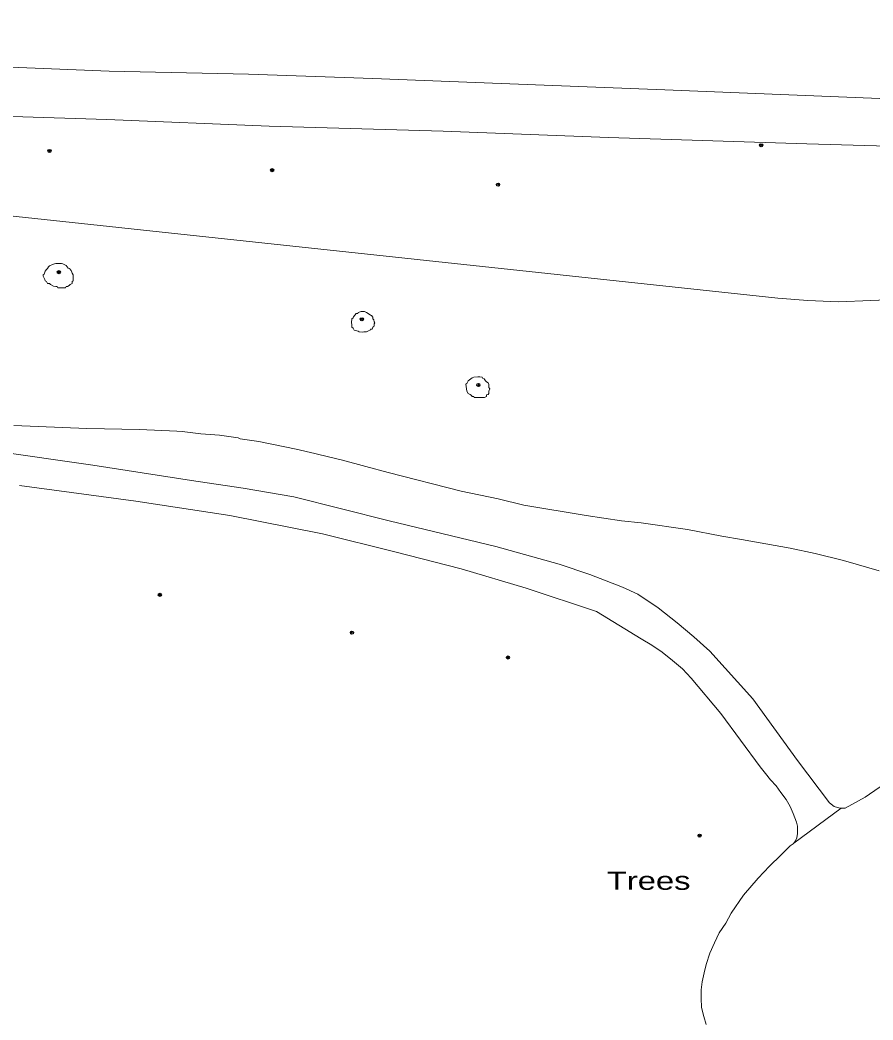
# Model space of a CAD drawing. Extents: x 528790 to 529292, y 179350 to 179856.
# Drawn here: x 528872.6 to 528954.9, y 179684.2 to 179780.7 of the extents above; entities that cross this region are included whole.
import ezdxf

# ---------------------------------------------------------------- set-up
doc = ezdxf.new("R2010")
doc.units = 0
doc.header["$LTSCALE"] = 0.6
doc.header["$PDMODE"] = 32
doc.header["$PDSIZE"] = 0.3
doc.layers.add('1', color=7, linetype='Continuous', lineweight=13)
doc.layers.add('2', color=7, linetype='Continuous', lineweight=13)
doc.layers.add('3', color=7, linetype='Continuous')
doc.layers.add('5', color=7, linetype='Continuous')

msp = doc.modelspace()

# ---------------------------------------------------------------- linework, layer by layer
at = {"layer": '1'}
for points in [[(528995.96, 179785.29), (528808.03, 179792.34), (528790.22, 179792.969), (528790.22, 179779.158), (528797.95, 179778.9), (528811.7, 179778.4), (528825.8, 179777.8), (528841.4, 179777.2), (528857, 179776.75), (528870, 179776.25), (528881.15, 179775.8), (528894.6, 179775.5), (528906.6, 179775.1), (528919, 179774.6), (528934.8, 179774), (528959.55, 179773)], [(528959.55, 179773), (528934.8, 179774), (528919, 179774.6), (528906.6, 179775.1), (528894.6, 179775.5), (528881.15, 179775.8), (528870, 179776.25), (528857, 179776.75), (528841.4, 179777.2), (528825.8, 179777.8), (528811.7, 179778.4), (528797.95, 179778.9), (528790.22, 179779.158), (528790.22, 179774.277), (528823.7, 179773.15), (528843.9, 179772.4), (528859.6, 179771.8), (528880.95, 179771.15), (528896.6, 179770.5), (528913.4, 179770), (528929.35, 179769.4), (528948.5, 179768.8), (528965.3, 179768.3)], [(528965.3, 179768.3), (528948.5, 179768.8), (528929.35, 179769.4), (528913.4, 179770), (528896.6, 179770.5), (528880.95, 179771.15), (528859.6, 179771.8), (528843.9, 179772.4), (528823.7, 179773.15), (528790.22, 179774.277), (528790.22, 179770.55), (528945.7, 179753.9), (528948.6, 179753.65), (528951.55, 179753.55), (528957.8, 179753.8)], [(528957.8, 179753.8), (528951.55, 179753.55), (528948.6, 179753.65), (528945.7, 179753.9), (528790.22, 179770.55)], [(528955.5, 179727.55), (528952.05, 179728.55), (528949.3, 179729.25), (528946.9, 179729.75), (528942.2, 179730.6), (528940.3, 179730.9), (528937, 179731.55), (528932.5, 179732.2), (528930.6, 179732.4), (528927.2, 179732.9), (528921.2, 179733.9), (528918.7, 179734.5), (528915.15, 179735.25), (528908.1, 179737.05), (528905.95, 179737.65), (528903.7, 179738.25), (528901.4, 179738.8), (528901, 179738.9), (528899.2, 179739.3), (528895.6, 179740.05), (528893.8, 179740.3), (528893.6, 179740.4), (528891.8, 179740.65), (528890, 179740.8), (528888.2, 179741), (528887.7, 179741.05), (528884.1, 179741.2), (528879, 179741.3), (528871.95, 179741.6)], [(528871.95, 179741.6), (528879, 179741.3), (528884.1, 179741.2), (528887.7, 179741.05), (528888.2, 179741), (528890, 179740.8), (528891.8, 179740.65), (528893.6, 179740.4), (528893.8, 179740.3), (528895.6, 179740.05), (528899.2, 179739.3), (528901, 179738.9), (528901.4, 179738.8), (528903.7, 179738.25), (528905.95, 179737.65), (528908.1, 179737.05), (528915.15, 179735.25), (528918.7, 179734.5), (528921.2, 179733.9), (528927.2, 179732.9), (528930.6, 179732.4), (528932.5, 179732.2), (528937, 179731.55), (528940.3, 179730.9), (528942.2, 179730.6), (528946.9, 179729.75), (528949.3, 179729.25), (528952.05, 179728.55), (528955.5, 179727.55)], [(528869.9, 179739.15), (528879.6, 179737.75), (528889.1, 179736.3), (528894.1, 179735.55), (528899, 179734.7), (528908.2, 179732.4), (528918.5, 179729.9), (528924.6, 179728.2), (528927.55, 179727.2), (528929.15, 179726.6), (528930.7, 179726), (528932.2, 179725.3), (528934.15, 179724), (528936, 179722.55), (528937.6, 179721.2), (528939.15, 179719.8), (528943.3, 179715.2), (528947.6, 179709.25), (528950.7, 179705.15), (528951.15, 179704.8), (528951.7, 179704.65), (528951.82, 179704.65), (528952.2, 179704.65), (528954.15, 179705.7), (528955.5, 179706.65)], [(528872.5, 179735.8), (528883.75, 179734.3), (528892.8, 179732.9), (528901.75, 179731.15), (528908.75, 179729.4), (528915.15, 179727.75), (528921.4, 179725.9), (528928.2, 179723.65), (528932.5, 179721), (528933.55, 179720.4), (528934.55, 179719.7), (528935.55, 179718.9), (528936.5, 179718.1), (528937.35, 179717.2), (528940.2, 179713.8), (528944, 179708.65), (528944.5, 179708), (528945, 179707.4), (528945.55, 179706.8), (528946, 179706.15), (528946.5, 179705.5), (528946.9, 179704.8), (528947.2, 179704.15), (528947.5, 179703.3), (528947.6, 179702.9), (528947.6, 179702.2), (528947.55, 179701.8), (528947.4, 179701.5), (528947.24, 179701.26), (528951.82, 179704.65), (528951.7, 179704.65), (528951.15, 179704.8), (528950.7, 179705.15), (528947.6, 179709.25), (528943.3, 179715.2), (528939.15, 179719.8), (528937.6, 179721.2), (528936, 179722.55), (528934.15, 179724), (528932.2, 179725.3), (528930.7, 179726), (528929.15, 179726.6), (528927.55, 179727.2), (528924.6, 179728.2), (528918.5, 179729.9), (528908.2, 179732.4), (528899, 179734.7), (528894.1, 179735.55), (528889.1, 179736.3), (528879.6, 179737.75), (528869.9, 179739.15)], [(528938.8, 179683.75), (528938.55, 179684.55), (528938.35, 179685.4), (528938.3, 179686.3), (528938.3, 179687.1), (528938.4, 179687.9), (528938.6, 179688.75), (528938.8, 179689.55), (528939.15, 179690.65), (528939.6, 179691.65), (528940.05, 179692.6), (528940.7, 179693.55), (528941.2, 179694.5), (528942.4, 179696.25), (528943.8, 179697.9), (528944.9, 179699.05), (528946, 179700.1), (528946.9, 179701), (528947.2, 179701.2), (528947.24, 179701.26), (528947.4, 179701.5), (528947.55, 179701.8), (528947.6, 179702.2), (528947.6, 179702.9), (528947.5, 179703.3), (528947.2, 179704.15), (528946.9, 179704.8), (528946.5, 179705.5), (528946, 179706.15), (528945.55, 179706.8), (528945, 179707.4), (528944.5, 179708), (528944, 179708.65), (528940.2, 179713.8), (528937.35, 179717.2), (528936.5, 179718.1), (528935.55, 179718.9), (528934.55, 179719.7), (528933.55, 179720.4), (528932.5, 179721), (528928.2, 179723.65), (528921.4, 179725.9), (528915.15, 179727.75), (528908.75, 179729.4), (528901.75, 179731.15), (528892.8, 179732.9), (528883.75, 179734.3), (528872.5, 179735.8)], [(528955.5, 179706.65), (528954.15, 179705.7), (528952.2, 179704.65), (528951.82, 179704.65), (528947.24, 179701.26), (528947.2, 179701.2), (528946.9, 179701), (528946, 179700.1), (528944.9, 179699.05), (528943.8, 179697.9), (528942.4, 179696.25), (528941.2, 179694.5), (528940.7, 179693.55), (528940.05, 179692.6), (528939.6, 179691.65), (528939.15, 179690.65), (528938.8, 179689.55), (528938.6, 179688.75), (528938.4, 179687.9), (528938.3, 179687.1), (528938.3, 179686.3), (528938.35, 179685.4), (528938.55, 179684.55), (528938.8, 179683.75)]]:
    msp.add_lwpolyline(points, dxfattribs=at)
for points in [[(528875.1, 179755.5), (528875, 179755.55), (528874.95, 179755.7), (528874.8, 179756), (528874.8, 179756.15), (528874.9, 179756.2), (528875, 179756.5), (528875.1, 179756.65), (528875.2, 179756.75), (528875.3, 179756.9), (528875.4, 179757), (528875.7, 179757.15), (528875.9, 179757.2), (528876, 179757.25), (528876.2, 179757.25), (528876.55, 179757.25), (528876.7, 179757.2), (528877, 179757.05), (528877.1, 179756.9), (528877.2, 179756.8), (528877.35, 179756.75), (528877.4, 179756.65), (528877.5, 179756.55), (528877.55, 179756.4), (528877.6, 179756.3), (528877.7, 179756.15), (528877.7, 179755.55), (528877.6, 179755.5), (528877.6, 179755.3), (528877.4, 179755.2), (528877.3, 179755.1), (528877.15, 179755), (528877, 179755), (528876.95, 179754.9), (528876.2, 179754.9), (528876.15, 179755), (528876, 179755), (528875.8, 179755.05), (528875.5, 179755.2), (528875.4, 179755.3), (528875.2, 179755.3)], [(528876.95, 179754.9), (528877, 179755), (528877.15, 179755), (528877.3, 179755.1), (528877.4, 179755.2), (528877.6, 179755.3), (528877.6, 179755.5), (528877.7, 179755.55), (528877.7, 179756.15), (528877.6, 179756.3), (528877.55, 179756.4), (528877.5, 179756.55), (528877.4, 179756.65), (528877.35, 179756.75), (528877.2, 179756.8), (528877.1, 179756.9), (528877, 179757.05), (528876.7, 179757.2), (528876.55, 179757.25), (528876.2, 179757.25), (528876, 179757.25), (528875.9, 179757.2), (528875.7, 179757.15), (528875.4, 179757), (528875.3, 179756.9), (528875.2, 179756.75), (528875.1, 179756.65), (528875, 179756.5), (528874.9, 179756.2), (528874.8, 179756.15), (528874.8, 179756), (528874.95, 179755.7), (528875, 179755.55), (528875.1, 179755.5), (528875.2, 179755.3), (528875.4, 179755.3), (528875.5, 179755.2), (528875.8, 179755.05), (528876, 179755), (528876.15, 179755), (528876.2, 179754.9)], [(528905, 179752.4), (528905.15, 179752.4), (528905.2, 179752.5), (528905.5, 179752.6), (528905.8, 179752.6), (528906, 179752.5), (528906.15, 179752.4), (528906.4, 179752.25), (528906.5, 179752.2), (528906.6, 179752.05), (528906.6, 179751.9), (528906.7, 179751.8), (528906.75, 179751.6), (528906.8, 179751.5), (528906.75, 179751.4), (528906.75, 179751.25), (528906.7, 179751.15), (528906.6, 179751.1), (528906.55, 179750.9), (528906.4, 179750.9), (528906.35, 179750.8), (528906.2, 179750.75), (528906, 179750.65), (528905.75, 179750.65), (528905.6, 179750.6), (528905.3, 179750.65), (528905.2, 179750.7), (528904.8, 179750.8), (528904.7, 179751), (528904.6, 179751.1), (528904.6, 179751.3), (528904.55, 179751.55), (528904.6, 179751.9), (528904.7, 179752), (528904.75, 179752.1)], [(528906, 179750.65), (528906.2, 179750.75), (528906.35, 179750.8), (528906.4, 179750.9), (528906.55, 179750.9), (528906.6, 179751.1), (528906.7, 179751.15), (528906.75, 179751.25), (528906.75, 179751.4), (528906.8, 179751.5), (528906.75, 179751.6), (528906.7, 179751.8), (528906.6, 179751.9), (528906.6, 179752.05), (528906.5, 179752.2), (528906.4, 179752.25), (528906.15, 179752.4), (528906, 179752.5), (528905.8, 179752.6), (528905.5, 179752.6), (528905.2, 179752.5), (528905.15, 179752.4), (528905, 179752.4), (528904.75, 179752.1), (528904.7, 179752), (528904.6, 179751.9), (528904.55, 179751.55), (528904.6, 179751.3), (528904.6, 179751.1), (528904.7, 179751), (528904.8, 179750.8), (528905.2, 179750.7), (528905.3, 179750.65), (528905.6, 179750.6), (528905.75, 179750.65)], [(528917.4, 179744.3), (528917.6, 179744.4), (528917.6, 179744.55), (528917.75, 179744.6), (528917.8, 179744.7), (528917.8, 179744.9), (528917.9, 179745.15), (528917.8, 179745.25), (528917.8, 179745.55), (528917.75, 179745.7), (528917.6, 179745.8), (528917.5, 179745.9), (528917.35, 179746.1), (528917.2, 179746.15), (528917.15, 179746.25), (528916.95, 179746.3), (528916.75, 179746.3), (528916.35, 179746.25), (528916.2, 179746.2), (528915.95, 179746), (528915.8, 179745.9), (528915.7, 179745.65), (528915.6, 179745.6), (528915.7, 179744.9), (528915.8, 179744.7), (528916, 179744.6), (528916.15, 179744.5), (528916.2, 179744.4), (528916.35, 179744.4), (528916.4, 179744.3)], [(528916.15, 179744.5), (528916, 179744.6), (528915.8, 179744.7), (528915.7, 179744.9), (528915.6, 179745.6), (528915.7, 179745.65), (528915.8, 179745.9), (528915.95, 179746), (528916.2, 179746.2), (528916.35, 179746.25), (528916.75, 179746.3), (528916.95, 179746.3), (528917.15, 179746.25), (528917.2, 179746.15), (528917.35, 179746.1), (528917.5, 179745.9), (528917.6, 179745.8), (528917.75, 179745.7), (528917.8, 179745.55), (528917.8, 179745.25), (528917.9, 179745.15), (528917.8, 179744.9), (528917.8, 179744.7), (528917.75, 179744.6), (528917.6, 179744.55), (528917.6, 179744.4), (528917.4, 179744.3), (528916.4, 179744.3), (528916.35, 179744.4), (528916.2, 179744.4)]]:
    msp.add_lwpolyline(points, close=True, dxfattribs=at)
at = {"layer": '2'}
msp.add_line((528947.24, 179701.26), (528951.82, 179704.65), dxfattribs=at)
for points in [[(528790.22, 179779.158), (528797.95, 179778.9), (528811.7, 179778.4), (528825.8, 179777.8), (528841.4, 179777.2), (528857, 179776.75), (528870, 179776.25), (528881.15, 179775.8), (528894.6, 179775.5), (528906.6, 179775.1), (528919, 179774.6), (528934.8, 179774), (528959.55, 179773)], [(528790.22, 179774.277), (528823.7, 179773.15), (528843.9, 179772.4), (528859.6, 179771.8), (528880.95, 179771.15), (528896.6, 179770.5), (528913.4, 179770), (528929.35, 179769.4), (528948.5, 179768.8), (528965.3, 179768.3), (528977.883, 179767.816), (528980.9, 179767.7), (528988.1, 179767.35), (529000, 179767.03), (529025.95, 179766.25), (529028.05, 179766.15), (529028.95, 179766.05), (529029.6, 179766.05), (529029.75, 179766), (529029.8, 179765.9), (529030.2, 179765.6)], [(528790.22, 179770.55), (528945.7, 179753.9), (528948.6, 179753.65), (528951.55, 179753.55), (528957.8, 179753.8), (528964.2, 179754.4), (528972.37, 179756.13)], [(528871.95, 179741.6), (528879, 179741.3), (528884.1, 179741.2), (528887.7, 179741.05), (528888.2, 179741), (528890, 179740.8), (528891.8, 179740.65), (528893.6, 179740.4), (528893.8, 179740.3), (528895.6, 179740.05), (528899.2, 179739.3), (528901, 179738.9), (528901.4, 179738.8), (528903.7, 179738.25), (528905.95, 179737.65), (528908.1, 179737.05), (528915.15, 179735.25), (528918.7, 179734.5), (528921.2, 179733.9), (528927.2, 179732.9), (528930.6, 179732.4), (528932.5, 179732.2), (528937, 179731.55), (528940.3, 179730.9), (528942.2, 179730.6), (528946.9, 179729.75), (528949.3, 179729.25), (528952.05, 179728.55), (528955.5, 179727.55)], [(528869.9, 179739.15), (528879.6, 179737.75), (528889.1, 179736.3), (528894.1, 179735.55), (528899, 179734.7), (528908.2, 179732.4), (528918.5, 179729.9), (528924.6, 179728.2), (528927.55, 179727.2), (528929.15, 179726.6), (528930.7, 179726), (528932.2, 179725.3), (528934.15, 179724), (528936, 179722.55), (528937.6, 179721.2), (528939.15, 179719.8), (528943.3, 179715.2), (528947.6, 179709.25), (528950.7, 179705.15), (528951.15, 179704.8), (528951.7, 179704.65), (528951.82, 179704.65)], [(528872.5, 179735.8), (528883.75, 179734.3), (528892.8, 179732.9), (528901.75, 179731.15), (528908.75, 179729.4), (528915.15, 179727.75), (528921.4, 179725.9), (528928.2, 179723.65), (528932.5, 179721), (528933.55, 179720.4), (528934.55, 179719.7), (528935.55, 179718.9), (528936.5, 179718.1), (528937.35, 179717.2), (528940.2, 179713.8), (528944, 179708.65), (528944.5, 179708), (528945, 179707.4), (528945.55, 179706.8), (528946, 179706.15), (528946.5, 179705.5), (528946.9, 179704.8), (528947.2, 179704.15), (528947.5, 179703.3), (528947.6, 179702.9), (528947.6, 179702.2), (528947.55, 179701.8), (528947.4, 179701.5), (528947.24, 179701.26)], [(528951.82, 179704.65), (528952.2, 179704.65), (528954.15, 179705.7), (528955.5, 179706.65), (528956.95, 179707.5), (528958.4, 179708.25), (528959.4, 179708.7), (528960.4, 179709.1), (528961.4, 179709.4), (528962.2, 179709.6), (528963.05, 179709.7), (528963.95, 179709.75), (528964.8, 179709.7), (528965.4, 179709.65), (528966.15, 179709.6), (528966.8, 179709.4), (528967.4, 179709.25), (528967.95, 179708.9), (528968.4, 179708.55), (528968.8, 179708.2), (528969.4, 179707.9), (528969.9, 179707.75)], [(528947.24, 179701.26), (528947.2, 179701.2), (528946.9, 179701), (528946, 179700.1), (528944.9, 179699.05), (528943.8, 179697.9), (528942.4, 179696.25), (528941.2, 179694.5), (528940.7, 179693.55), (528940.05, 179692.6), (528939.6, 179691.65), (528939.15, 179690.65), (528938.8, 179689.55), (528938.6, 179688.75), (528938.4, 179687.9), (528938.3, 179687.1), (528938.3, 179686.3), (528938.35, 179685.4), (528938.55, 179684.55), (528938.8, 179683.75)]]:
    msp.add_lwpolyline(points, dxfattribs=at)
for points in [[(528876.95, 179754.9), (528876.2, 179754.9), (528876.15, 179755), (528876, 179755), (528875.8, 179755.05), (528875.5, 179755.2), (528875.4, 179755.3), (528875.2, 179755.3), (528875.1, 179755.5), (528875, 179755.55), (528874.95, 179755.7), (528874.8, 179756), (528874.8, 179756.15), (528874.9, 179756.2), (528875, 179756.5), (528875.1, 179756.65), (528875.2, 179756.75), (528875.3, 179756.9), (528875.4, 179757), (528875.7, 179757.15), (528875.9, 179757.2), (528876, 179757.25), (528876.2, 179757.25), (528876.55, 179757.25), (528876.7, 179757.2), (528877, 179757.05), (528877.1, 179756.9), (528877.2, 179756.8), (528877.35, 179756.75), (528877.4, 179756.65), (528877.5, 179756.55), (528877.55, 179756.4), (528877.6, 179756.3), (528877.7, 179756.15), (528877.7, 179755.55), (528877.6, 179755.5), (528877.6, 179755.3), (528877.4, 179755.2), (528877.3, 179755.1), (528877.15, 179755), (528877, 179755)], [(528906, 179750.65), (528905.75, 179750.65), (528905.6, 179750.6), (528905.3, 179750.65), (528905.2, 179750.7), (528904.8, 179750.8), (528904.7, 179751), (528904.6, 179751.1), (528904.6, 179751.3), (528904.55, 179751.55), (528904.6, 179751.9), (528904.7, 179752), (528904.75, 179752.1), (528905, 179752.4), (528905.15, 179752.4), (528905.2, 179752.5), (528905.5, 179752.6), (528905.8, 179752.6), (528906, 179752.5), (528906.15, 179752.4), (528906.4, 179752.25), (528906.5, 179752.2), (528906.6, 179752.05), (528906.6, 179751.9), (528906.7, 179751.8), (528906.75, 179751.6), (528906.8, 179751.5), (528906.75, 179751.4), (528906.75, 179751.25), (528906.7, 179751.15), (528906.6, 179751.1), (528906.55, 179750.9), (528906.4, 179750.9), (528906.35, 179750.8), (528906.2, 179750.75)], [(528917.4, 179744.3), (528916.4, 179744.3), (528916.35, 179744.4), (528916.2, 179744.4), (528916.15, 179744.5), (528916, 179744.6), (528915.8, 179744.7), (528915.7, 179744.9), (528915.6, 179745.6), (528915.7, 179745.65), (528915.8, 179745.9), (528915.95, 179746), (528916.2, 179746.2), (528916.35, 179746.25), (528916.75, 179746.3), (528916.95, 179746.3), (528917.15, 179746.25), (528917.2, 179746.15), (528917.35, 179746.1), (528917.5, 179745.9), (528917.6, 179745.8), (528917.75, 179745.7), (528917.8, 179745.55), (528917.8, 179745.25), (528917.9, 179745.15), (528917.8, 179744.9), (528917.8, 179744.7), (528917.75, 179744.6), (528917.6, 179744.55), (528917.6, 179744.4)]]:
    msp.add_lwpolyline(points, close=True, dxfattribs=at)
at = {"layer": '3'}
for p in [(528944.1, 179768.65), (528875.4, 179768.1), (528896.9, 179766.25), (528918.7, 179764.85), (528876.3, 179756.4), (528905.55, 179751.85), (528916.8, 179745.5), (528886.05, 179725.25), (528904.6, 179721.6), (528919.65, 179719.2), (528938.15, 179702)]:
    msp.add_point(p, dxfattribs=at)

# ---------------------------------------------------------------- texts
at = {"layer": '5', "width": 1.35}
msp.add_text('Trees', height=1.75, dxfattribs=at).set_placement((528929.2, 179696.77))

doc.saveas('drawing.dxf')
